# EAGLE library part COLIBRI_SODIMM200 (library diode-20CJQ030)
TORADEX's Colibri So-Dimm 200 ModuleCDRH2D18/HP Intel XScale®Based SODIMMSizedComputer Colibri is a SODIMMsized computer module based on the new Intel XScale PXA270processor. It runs at up to 520 MHz and consumes as little as 800 mW. The power consumption is optimised using the new Wireless Intel Speedstep Technology. The module delivers state of the art technology, targeting low power systems that still require high CPU performance. It also offers all the interfaces needed in a modern embedded device. The module provides glueless connectivity to passive and active LCDs with resolutions of up to 800x600, as well as 4-wire resistive touch screens. An integrated 16 bit stereo codec allows Colibri to play and recordsound. Colibri can directly connect to a CCDcamera sensor, or take advantage of the new Intel Mobile Scalable Link that offers transfer speeds of upto416Mbps. In addition Colibri offers a 100 MBit Ethernet as well as USB host and USB device functionality. Flexibility andSecondSource Colibri can be scaled to meet specific cost requirements: Assembly options are available for Ethernet, Audio Codec, FLASHsize, RAMsize and CPUspeed. The entire 32 bit wide CPU bus is available for custom extensions, such as special interfaces for high bandwidth applications. Colibri Modules can be used as a replacement for Keith &Koep's Trizeps III / IV family of modules. Colibri comes with a pre-installedoperating systemand state of the art development tools that allow an easy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
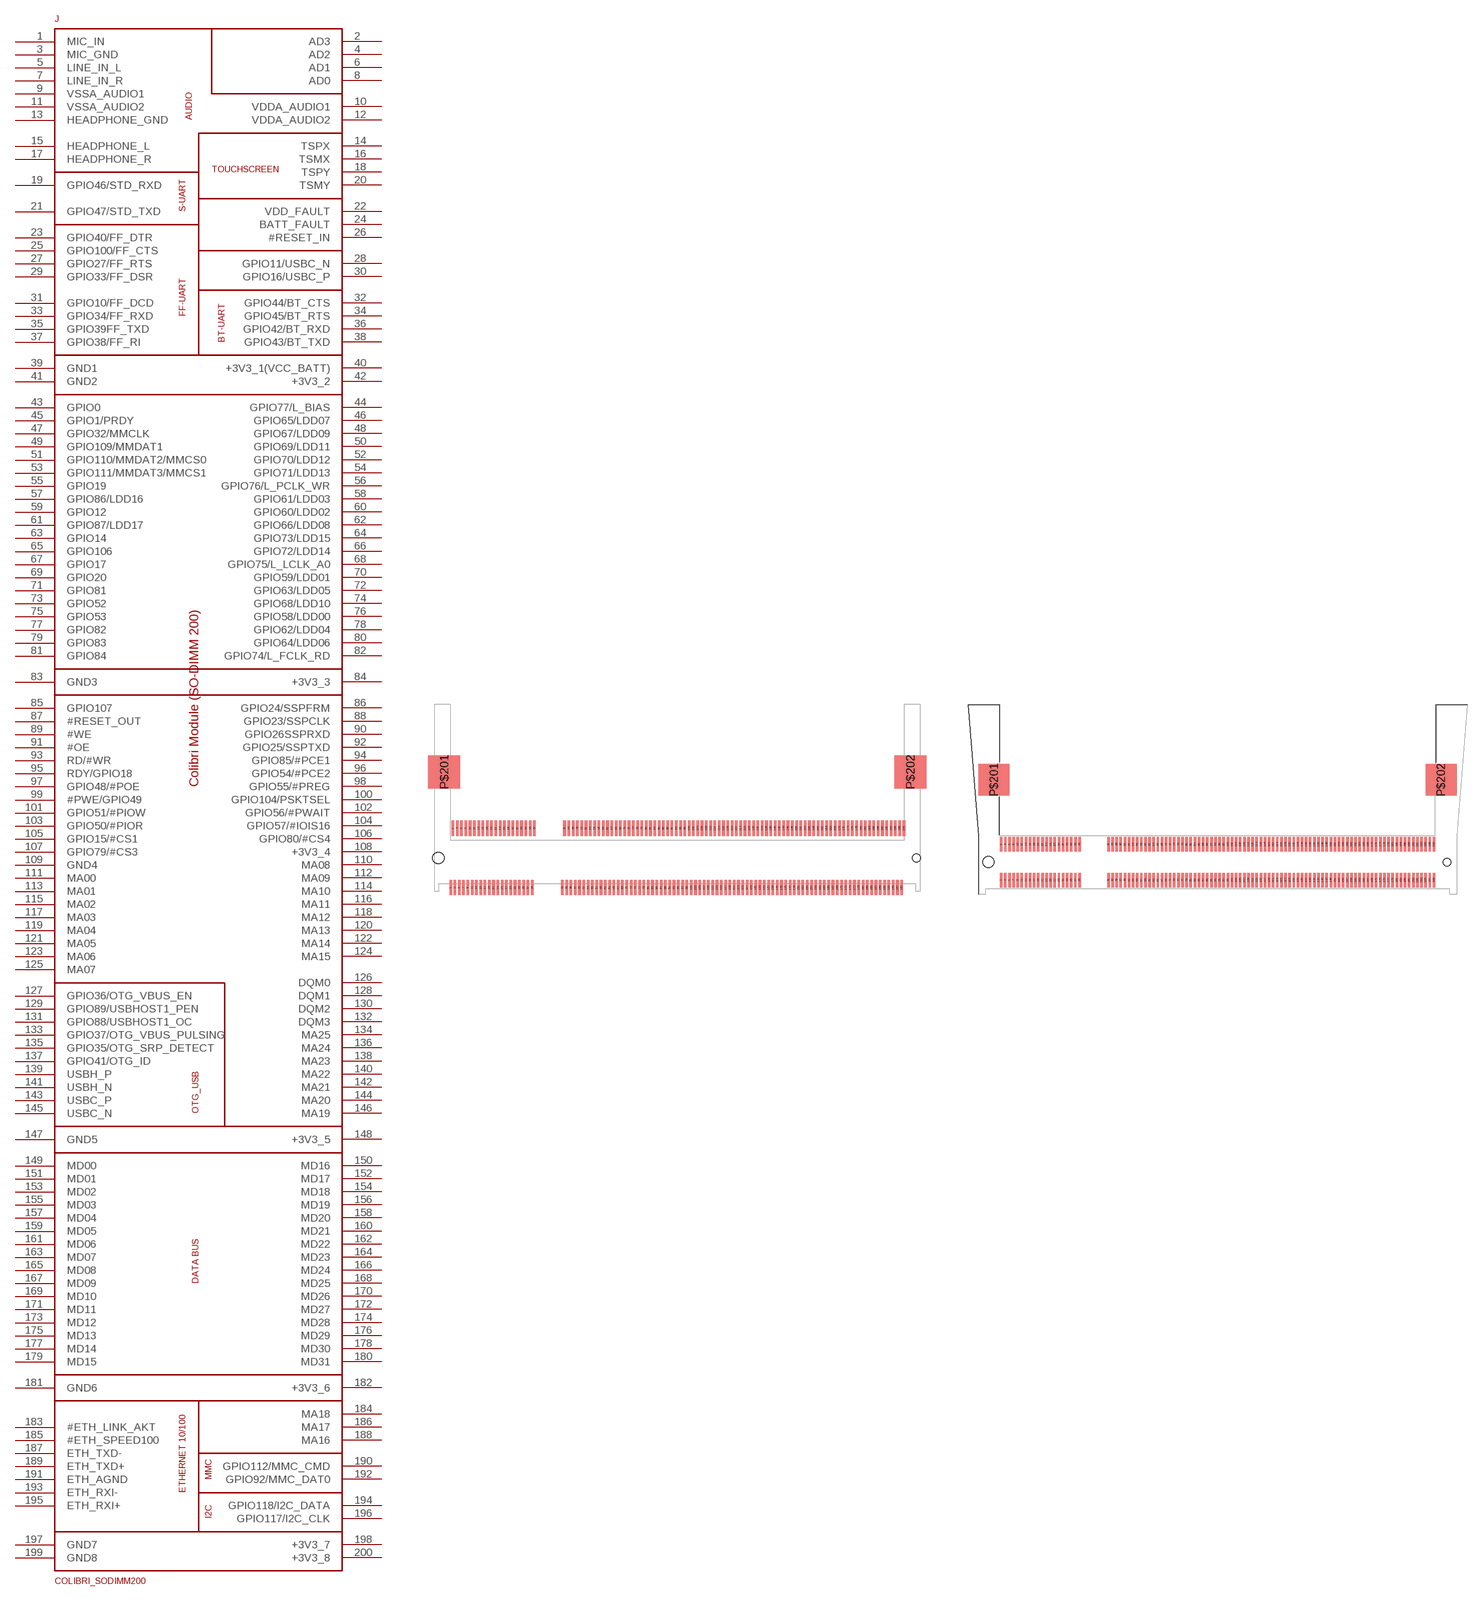
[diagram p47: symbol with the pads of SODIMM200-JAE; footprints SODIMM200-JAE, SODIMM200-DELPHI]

Designator prefix J

## COLIBRI_SODIMM200JAE  [SODIMM200-JAE]
1  MIC_IN  pas
2  AD3  pas
3  MIC_GND  pas
4  AD2  pas
5  LINE_IN_L  pas
6  AD1  pas
7  LINE_IN_R  pas
8  AD0  pas
9  VSSA_AUDIO1  pas
10  VDDA_AUDIO1  pas
11  VSSA_AUDIO2  pas
12  VDDA_AUDIO2  pas
13  HEADPHONE_GND  pas
14  TSPX  pas
15  HEADPHONE_L  pas
16  TSMX  pas
17  HEADPHONE_R  pas
18  TSPY  pas
19  GPIO46/STD_RXD  pas
20  TSMY  pas
21  GPIO47/STD_TXD  pas
22  VDD_FAULT  pas
23  GPIO40/FF_DTR  pas
24  BATT_FAULT  pas
25  GPIO100/FF_CTS  pas
26  #RESET_IN  pas
27  GPIO27/FF_RTS  pas
28  GPIO11/USBC_N  pas
29  GPIO33/FF_DSR  pas
30  GPIO16/USBC_P  pas
31  GPIO10/FF_DCD  pas
32  GPIO44/BT_CTS  pas
33  GPIO34/FF_RXD  pas
34  GPIO45/BT_RTS  pas
35  GPIO39FF_TXD  pas
36  GPIO42/BT_RXD  pas
37  GPIO38/FF_RI  pas
38  GPIO43/BT_TXD  pas
39  GND1  pas
40  +3V3_1(VCC_BATT)  pas
41  GND2  pas
42  +3V3_2  pas
43  GPIO0  pas
44  GPIO77/L_BIAS  pas
45  GPIO1/PRDY  pas
46  GPIO65/LDD07  pas
47  GPIO32/MMCLK  pas
48  GPIO67/LDD09  pas
49  GPIO109/MMDAT1  pas
50  GPIO69/LDD11  pas
51  GPIO110/MMDAT2/MMCS0  pas
52  GPIO70/LDD12  pas
53  GPIO111/MMDAT3/MMCS1  pas
54  GPIO71/LDD13  pas
55  GPIO19  pas
56  GPIO76/L_PCLK_WR  pas
57  GPIO86/LDD16  pas
58  GPIO61/LDD03  pas
59  GPIO12  pas
60  GPIO60/LDD02  pas
61  GPIO87/LDD17  pas
62  GPIO66/LDD08  pas
63  GPIO14  pas
64  GPIO73/LDD15  pas
65  GPIO106  pas
66  GPIO72/LDD14  pas
67  GPIO17  pas
68  GPIO75/L_LCLK_A0  pas
69  GPIO20  pas
70  GPIO59/LDD01  pas
71  GPIO81  pas
72  GPIO63/LDD05  pas
73  GPIO52  pas
74  GPIO68/LDD10  pas
75  GPIO53  pas
76  GPIO58/LDD00  pas
77  GPIO82  pas
78  GPIO62/LDD04  pas
79  GPIO83  pas
80  GPIO64/LDD06  pas
81  GPIO84  pas
82  GPIO74/L_FCLK_RD  pas
83  GND3  pas
84  +3V3_3  pas
85  GPIO107  pas
86  GPIO24/SSPFRM  pas
87  #RESET_OUT  pas
88  GPIO23/SSPCLK  pas
89  #WE  pas
90  GPIO26SSPRXD  pas
91  #OE  pas
92  GPIO25/SSPTXD  pas
93  RD/#WR  pas
94  GPIO85/#PCE1  pas
95  RDY/GPIO18  pas
96  GPIO54/#PCE2  pas
97  GPIO48/#POE  pas
98  GPIO55/#PREG  pas
99  #PWE/GPIO49  pas
100  GPIO104/PSKTSEL  pas
101  GPIO51/#PIOW  pas
102  GPIO56/#PWAIT  pas
103  GPIO50/#PIOR  pas
104  GPIO57/#IOIS16  pas
105  GPIO15/#CS1  pas
106  GPIO80/#CS4  pas
107  GPIO79/#CS3  pas
108  +3V3_4  pas
109  GND4  pas
110  MA08  pas
111  MA00  pas
112  MA09  pas
113  MA01  pas
114  MA10  pas
115  MA02  pas
116  MA11  pas
117  MA03  pas
118  MA12  pas
119  MA04  pas
120  MA13  pas
121  MA05  pas
122  MA14  pas
123  MA06  pas
124  MA15  pas
125  MA07  pas
126  DQM0  pas
127  GPIO36/OTG_VBUS_EN  pas
128  DQM1  pas
129  GPIO89/USBHOST1_PEN  pas
130  DQM2  pas
131  GPIO88/USBHOST1_OC  pas
132  DQM3  pas
133  GPIO37/OTG_VBUS_PULSING  pas
134  MA25  pas
135  GPIO35/OTG_SRP_DETECT  pas
136  MA24  pas
137  GPIO41/OTG_ID  pas
138  MA23  pas
139  USBH_P  pas
140  MA22  pas
141  USBH_N  pas
142  MA21  pas
143  USBC_P  pas
144  MA20  pas
145  USBC_N  pas
146  MA19  pas
147  GND5  pas
148  +3V3_5  pas
149  MD00  pas
150  MD16  pas
151  MD01  pas
152  MD17  pas
153  MD02  pas
154  MD18  pas
155  MD03  pas
156  MD19  pas
157  MD04  pas
158  MD20  pas
159  MD05  pas
160  MD21  pas
161  MD06  pas
162  MD22  pas
163  MD07  pas
164  MD23  pas
165  MD08  pas
166  MD24  pas
167  MD09  pas
168  MD25  pas
169  MD10  pas
170  MD26  pas
171  MD11  pas
172  MD27  pas
173  MD12  pas
174  MD28  pas
175  MD13  pas
176  MD29  pas
177  MD14  pas
178  MD30  pas
179  MD15  pas
180  MD31  pas
181  GND6  pas
182  +3V3_6  pas
183  #ETH_LINK_AKT  pas
184  MA18  pas
185  #ETH_SPEED100  pas
186  MA17  pas
187  ETH_TXD-  pas
188  MA16  pas
189  ETH_TXD+  pas
190  GPIO112/MMC_CMD  pas
191  ETH_AGND  pas
192  GPIO92/MMC_DAT0  pas
193  ETH_RXI-  pas
194  GPIO118/I2C_DATA  pas
195  ETH_RXI+  pas
196  GPIO117/I2C_CLK  pas
197  GND7  pas
198  +3V3_7  pas
199  GND8  pas
200  +3V3_8  pas

## COLIBRI_SODIMM200DELPHI  [SODIMM200-DELPHI]
Pads as for SODIMM200-JAE

## Footprint SODIMM200-JAE (pad centres in mm)
JAE-Connector So-Dimm 200 Connector MM50 - 200B* - *
smd 0.36 x 2.1: 1 -31.65,-4.15; 2 -31.34,4.15; 3 -31.05,-4.15; 4 -30.74,4.15; 5 -30.45,-4.15; 6 -30.14,4.15; 7 -29.85,-4.15; 8 -29.54,4.15; 9 -29.25,-4.15; 10 -28.94,4.15; 11 -28.65,-4.15; 12 -28.34,4.15; 13 -28.05,-4.15; 14 -27.74,4.15; 15 -27.45,-4.15; 16 -27.14,4.15; 17 -26.85,-4.15; 18 -26.54,4.15; 19 -26.25,-4.15; 20 -25.94,4.15; 21 -25.65,-4.15; 22 -25.34,4.15; 23 -25.05,-4.15; 24 -24.74,4.15; 25 -24.45,-4.15; 26 -24.14,4.15; 27 -23.85,-4.15; 28 -23.54,4.15; 29 -23.25,-4.15; 30 -22.94,4.15; 31 -22.65,-4.15; 32 -22.34,4.15; 33 -22.05,-4.15; 34 -21.74,4.15; 35 -21.45,-4.15; 36 -21.14,4.15; 37 -20.85,-4.15; 38 -20.54,4.15; 39 -20.25,-4.15; 40 -19.94,4.15; 41 -16.04,-4.15; 42 -15.74,4.15; 43 -15.45,-4.15; 44 -15.14,4.15; 45 -14.85,-4.15; 46 -14.54,4.15; 47 -14.25,-4.15; 48 -13.94,4.15; 49 -13.65,-4.15; 50 -13.34,4.15; 51 -13.05,-4.15; 52 -12.74,4.15; 53 -12.45,-4.15; 54 -12.14,4.15; 55 -11.85,-4.15; 56 -11.54,4.15; 57 -11.25,-4.15; 58 -10.94,4.15; 59 -10.65,-4.15; 60 -10.34,4.15; 61 -10.05,-4.15; 62 -9.74,4.15; 63 -9.45,-4.15; 64 -9.14,4.15; 65 -8.85,-4.15; 66 -8.54,4.15; 67 -8.25,-4.15; 68 -7.94,4.15; 69 -7.65,-4.15; 70 -7.34,4.15; 71 -7.05,-4.15; 72 -6.74,4.15; 73 -6.45,-4.15; 74 -6.14,4.15; 75 -5.85,-4.15; 76 -5.54,4.15; 77 -5.25,-4.15; 78 -4.94,4.15; 79 -4.65,-4.15; 80 -4.34,4.15; 81 -4.05,-4.15; 82 -3.74,4.15; 83 -3.45,-4.15; 84 -3.14,4.15; 85 -2.85,-4.15; 86 -2.54,4.15; 87 -2.25,-4.15; 88 -1.94,4.15; 89 -1.65,-4.15; 90 -1.34,4.15; 91 -1.05,-4.15; 92 -0.74,4.15; 93 -0.45,-4.15; 94 -0.14,4.15; 95 0.15,-4.15; 96 0.46,4.15; 97 0.75,-4.15; 98 1.06,4.15; 99 1.35,-4.15; 100 1.66,4.15; 101 1.95,-4.15; 102 2.26,4.15; 103 2.55,-4.15; 104 2.86,4.15; 105 3.15,-4.15; 106 3.46,4.15; 107 3.75,-4.15; 108 4.06,4.15; 109 4.35,-4.15; 110 4.66,4.15; 111 4.95,-4.15; 112 5.26,4.15; 113 5.55,-4.15; 114 5.86,4.15; 115 6.15,-4.15; 116 6.46,4.15; 117 6.75,-4.15; 118 7.06,4.15; 119 7.35,-4.15; 120 7.66,4.15; 121 7.95,-4.15; 122 8.26,4.15; 123 8.55,-4.15; 124 8.86,4.15; 125 9.15,-4.15; 126 9.46,4.15; 127 9.75,-4.15; 128 10.06,4.15; 129 10.35,-4.15; 130 10.66,4.15; 131 10.95,-4.15; 132 11.26,4.15; 133 11.55,-4.15; 134 11.86,4.15; 135 12.15,-4.15; 136 12.46,4.15; 137 12.75,-4.15; 138 13.06,4.15; 139 13.35,-4.15; 140 13.66,4.15; 141 13.95,-4.15; 142 14.26,4.15; 143 14.55,-4.15; 144 14.86,4.15; 145 15.15,-4.15; 146 15.46,4.15; 147 15.75,-4.15; 148 16.06,4.15; 149 16.35,-4.15; 150 16.66,4.15; 151 16.95,-4.15; 152 17.26,4.15; 153 17.55,-4.15; 154 17.86,4.15; 155 18.15,-4.15; 156 18.46,4.15; 157 18.75,-4.15; 158 19.06,4.15; 159 19.35,-4.15; 160 19.66,4.15; 161 19.95,-4.15; 162 20.26,4.15; 163 20.55,-4.15; 164 20.86,4.15; 165 21.15,-4.15; 166 21.46,4.15; 167 21.75,-4.15; 168 22.06,4.15; 169 22.35,-4.15; 170 22.66,4.15; 171 22.95,-4.15; 172 23.26,4.15; 173 23.55,-4.15; 174 23.86,4.15; 175 24.15,-4.15; 176 24.46,4.15; 177 24.75,-4.15; 178 25.06,4.15; 179 25.35,-4.15; 180 25.66,4.15; 181 25.95,-4.15; 182 26.26,4.15; 183 26.55,-4.15; 184 26.86,4.15; 185 27.15,-4.15; 186 27.46,4.15; 187 27.75,-4.15; 188 28.06,4.15; 189 28.35,-4.15; 190 28.66,4.15; 191 28.95,-4.15; 192 29.26,4.15; 193 29.55,-4.15; 194 29.86,4.15; 195 30.15,-4.15; 196 30.46,4.15; 197 30.75,-4.15; 198 31.06,4.15; 199 31.35,-4.15; 200 31.66,4.15
smd 4.5 x 4.6: P$201 -32.55,12; P$202 32.55,12
hole 1.6 at -33.4,0
hole 1.1 at 33.4,0

## Footprint SODIMM200-DELPHI (pad centres in mm)
smd 0.36 x 2.1: 1 -31.51,-2.6; 2 -31.5,2.6; 3 -30.91,-2.6; 4 -30.9,2.6; 5 -30.31,-2.6; 6 -30.3,2.6; 7 -29.71,-2.6; 8 -29.7,2.6; 9 -29.11,-2.6; 10 -29.1,2.6; 11 -28.51,-2.6; 12 -28.5,2.6; 13 -27.91,-2.6; 14 -27.9,2.6; 15 -27.31,-2.6; 16 -27.3,2.6; 17 -26.71,-2.6; 18 -26.7,2.6; 19 -26.11,-2.6; 20 -26.1,2.6; 21 -25.51,-2.6; 22 -25.5,2.6; 23 -24.91,-2.6; 24 -24.9,2.6; 25 -24.31,-2.6; 26 -24.3,2.6; 27 -23.71,-2.6; 28 -23.7,2.6; 29 -23.11,-2.6; 30 -23.1,2.6; 31 -22.51,-2.6; 32 -22.5,2.6; 33 -21.91,-2.6; 34 -21.9,2.6; 35 -21.31,-2.6; 36 -21.3,2.6; 37 -20.71,-2.6; 38 -20.7,2.6; 39 -20.11,-2.6; 40 -20.1,2.6; 41 -15.9,-2.6; 42 -15.9,2.6; 43 -15.3,-2.6; 44 -15.3,2.6; 45 -14.7,-2.6; 46 -14.7,2.6; 47 -14.1,-2.6; 48 -14.1,2.6; 49 -13.5,-2.6; 50 -13.5,2.6; 51 -12.9,-2.6; 52 -12.9,2.6; 53 -12.3,-2.6; 54 -12.3,2.6; 55 -11.7,-2.6; 56 -11.7,2.6; 57 -11.1,-2.6; 58 -11.1,2.6; 59 -10.5,-2.6; 60 -10.5,2.6; 61 -9.9,-2.6; 62 -9.9,2.6; 63 -9.3,-2.6; 64 -9.3,2.6; 65 -8.7,-2.6; 66 -8.7,2.6; 67 -8.1,-2.6; 68 -8.1,2.6; 69 -7.5,-2.6; 70 -7.5,2.6; 71 -6.9,-2.6; 72 -6.9,2.6; 73 -6.3,-2.6; 74 -6.3,2.6; 75 -5.7,-2.6; 76 -5.7,2.6; 77 -5.1,-2.6; 78 -5.1,2.6; 79 -4.5,-2.6; 80 -4.5,2.6; 81 -3.9,-2.6; 82 -3.9,2.6; 83 -3.3,-2.6; 84 -3.3,2.6; 85 -2.7,-2.6; 86 -2.7,2.6; 87 -2.1,-2.6; 88 -2.1,2.6; 89 -1.5,-2.6; 90 -1.5,2.6; 91 -0.9,-2.6; 92 -0.9,2.6; 93 -0.3,-2.6; 94 -0.3,2.6; 95 0.3,-2.6; 96 0.3,2.6; 97 0.9,-2.6; 98 0.9,2.6; 99 1.5,-2.6; 100 1.5,2.6; 101 2.1,-2.6; 102 2.1,2.6; 103 2.7,-2.6; 104 2.7,2.6; 105 3.3,-2.6; 106 3.3,2.6; 107 3.9,-2.6; 108 3.9,2.6; 109 4.5,-2.6; 110 4.5,2.6; 111 5.1,-2.6; 112 5.1,2.6; 113 5.7,-2.6; 114 5.7,2.6; 115 6.3,-2.6; 116 6.3,2.6; 117 6.9,-2.6; 118 6.9,2.6; 119 7.5,-2.6; 120 7.5,2.6; 121 8.1,-2.6; 122 8.1,2.6; 123 8.7,-2.6; 124 8.7,2.6; 125 9.3,-2.6; 126 9.3,2.6; 127 9.9,-2.6; 128 9.9,2.6; 129 10.5,-2.6; 130 10.5,2.6; 131 11.1,-2.6; 132 11.1,2.6; 133 11.7,-2.6; 134 11.7,2.6; 135 12.3,-2.6; 136 12.3,2.6; 137 12.9,-2.6; 138 12.9,2.6; 139 13.5,-2.6; 140 13.5,2.6; 141 14.1,-2.6; 142 14.1,2.6; 143 14.7,-2.6; 144 14.7,2.6; 145 15.3,-2.6; 146 15.3,2.6; 147 15.9,-2.6; 148 15.9,2.6; 149 16.5,-2.6; 150 16.5,2.6; 151 17.1,-2.6; 152 17.1,2.6; 153 17.7,-2.6; 154 17.7,2.6; 155 18.3,-2.6; 156 18.3,2.6; 157 18.9,-2.6; 158 18.9,2.6; 159 19.5,-2.6; 160 19.5,2.6; 161 20.1,-2.6; 162 20.1,2.6; 163 20.7,-2.6; 164 20.7,2.6; 165 21.3,-2.6; 166 21.3,2.6; 167 21.9,-2.6; 168 21.9,2.6; 169 22.5,-2.6; 170 22.5,2.6; 171 23.1,-2.6; 172 23.1,2.6; 173 23.7,-2.6; 174 23.7,2.6; 175 24.3,-2.6; 176 24.3,2.6; 177 24.9,-2.6; 178 24.9,2.6; 179 25.5,-2.6; 180 25.5,2.6; 181 26.1,-2.6; 182 26.1,2.6; 183 26.7,-2.6; 184 26.7,2.6; 185 27.3,-2.6; 186 27.3,2.6; 187 27.9,-2.6; 188 27.9,2.6; 189 28.5,-2.6; 190 28.5,2.6; 191 29.1,-2.6; 192 29.1,2.6; 193 29.7,-2.6; 194 29.7,2.6; 195 30.3,-2.6; 196 30.3,2.6; 197 30.9,-2.6; 198 30.9,2.6; 199 31.5,-2.6; 200 31.5,2.6
smd 4.5 x 4.6: P$201 -32.55,12; P$202 32.55,12
hole 1.1 at 33.4,0
hole 1.6 at -33.4,0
